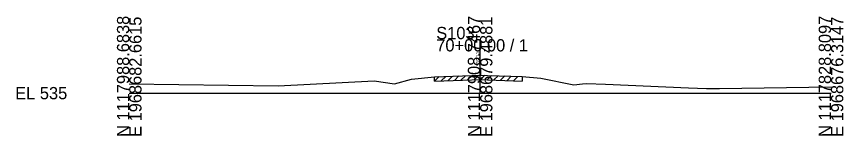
# Model space of a CAD drawing. Extents: x -26 to 163, y -10 to 45020.
# Drawn here: x -25.7 to 162.8, y 28990.3 to 29017.5 of the extents above; entities that cross this region are included whole.
import ezdxf

# ---------------------------------------------------------------- set-up
doc = ezdxf.new("R2010")
doc.units = 0
for name, color, linetype in [('RD_GPK_XS_Cell', 7, 'Continuous'), ('RD_XS_ExGround', 7, 'Continuous'), ('RD_XS_ExPaveRet', 7, 'Continuous'), ('RD_XS_TX_Elev_EX', 7, 'Continuous')]:
    doc.layers.add(name, color=color, linetype=linetype)

msp = doc.modelspace()

# ---------------------------------------------------------------- linework, layer by layer
at = {"layer": 'RD_GPK_XS_Cell'}
for p, q in [((80, 29000), (80, 29012.34)), ((0, 29000), (80, 29000)), ((80, 29000), (160, 29000))]:
    msp.add_line(p, q, dxfattribs=at)
at = {"layer": 'RD_XS_ExGround'}
for p, q in [((69.63, 29003.74), (75.97, 29003.96)), ((75.97, 29003.96), (80.14, 29004.11)), ((80.14, 29004.11), (81.66, 29004.06)), ((81.66, 29004.06), (89.61, 29003.77)), ((0, 29002.15), (33.98, 29001.68)), ((33.98, 29001.68), (55.86, 29002.84)), ((55.86, 29002.84), (60.51, 29002.13)), ((60.51, 29002.13), (64.34, 29003.21)), ((64.34, 29003.21), (69.63, 29003.74)), ((89.61, 29003.77), (93.87, 29003.39)), ((93.87, 29003.39), (101.36, 29001.89)), ((101.36, 29001.89), (103.33, 29002.1)), ((103.33, 29002.1), (104.26, 29002.2)), ((104.26, 29002.2), (108.58, 29002.02)), ((108.58, 29002.02), (127.49, 29001.22)), ((127.49, 29001.22), (131.62, 29001.04)), ((131.62, 29001.04), (134.56, 29001.08)), ((134.56, 29001.08), (160, 29001.47))]:
    msp.add_line(p, q, dxfattribs=at)
at = {"layer": 'RD_XS_ExPaveRet'}
for p, q in [((72.63, 29002.85), (73.67, 29003.88)), ((74.13, 29002.9), (75.17, 29003.94)), ((75.63, 29002.95), (76.67, 29003.99)), ((77.13, 29003.01), (78.17, 29004.04)), ((78.63, 29003.06), (79.67, 29004.1)), ((80.13, 29003.11), (81.1, 29004.08)), ((81.63, 29003.06), (82.6, 29004.03)), ((83.13, 29003.01), (84.1, 29003.97)), ((84.63, 29002.95), (85.6, 29003.92)), ((86.13, 29002.9), (87.1, 29003.86)), ((69.63, 29002.74), (70.67, 29003.78)), ((69.63, 29002.74), (69.63, 29003.74)), ((69.63, 29002.74), (75.97, 29002.96)), ((71.13, 29002.79), (72.17, 29003.83)), ((75.97, 29002.96), (80.14, 29003.11)), ((80.14, 29003.11), (81.66, 29003.06)), ((81.66, 29003.06), (89.61, 29002.77)), ((87.63, 29002.84), (88.6, 29003.81)), ((89.61, 29003.77), (89.61, 29002.77))]:
    msp.add_line(p, q, dxfattribs=at)

# ---------------------------------------------------------------- texts
at = {"layer": 'RD_GPK_XS_Cell'}
for s, p in [('N 1117988.6838', (0, 28990)), ('E 1968682.6615', (2.8, 28990)), ('N 1117908.7467', (80, 28990)), ('E 1968679.4881', (82.8, 28990)), ('N 1117828.8097', (160, 28990)), ('E 1968676.3147', (162.8, 28990))]:
    msp.add_text(s, height=2.8, rotation=90, dxfattribs=at).set_placement(p)
for s, p in [('S103', (70, 29012.34)), ('70+00.00 / 1', (70, 29009.54)), ('EL 535', (-26, 28998.6))]:
    msp.add_text(s, height=2.8, dxfattribs=at).set_placement(p)
at = {"layer": 'RD_XS_TX_Elev_EX'}
msp.add_text('539.11', height=0.8, rotation=90, dxfattribs=at).set_placement((79.9, 29006.11))

doc.saveas('drawing.dxf')
